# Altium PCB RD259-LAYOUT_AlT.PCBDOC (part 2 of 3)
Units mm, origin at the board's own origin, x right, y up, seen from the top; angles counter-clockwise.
Board outline 82.5 x 69.38 mm, 2 copper layers (TOP, BOTTOM), stack 0 mm thick; 80 components, 51 nets, 446 pads, 0 vias.
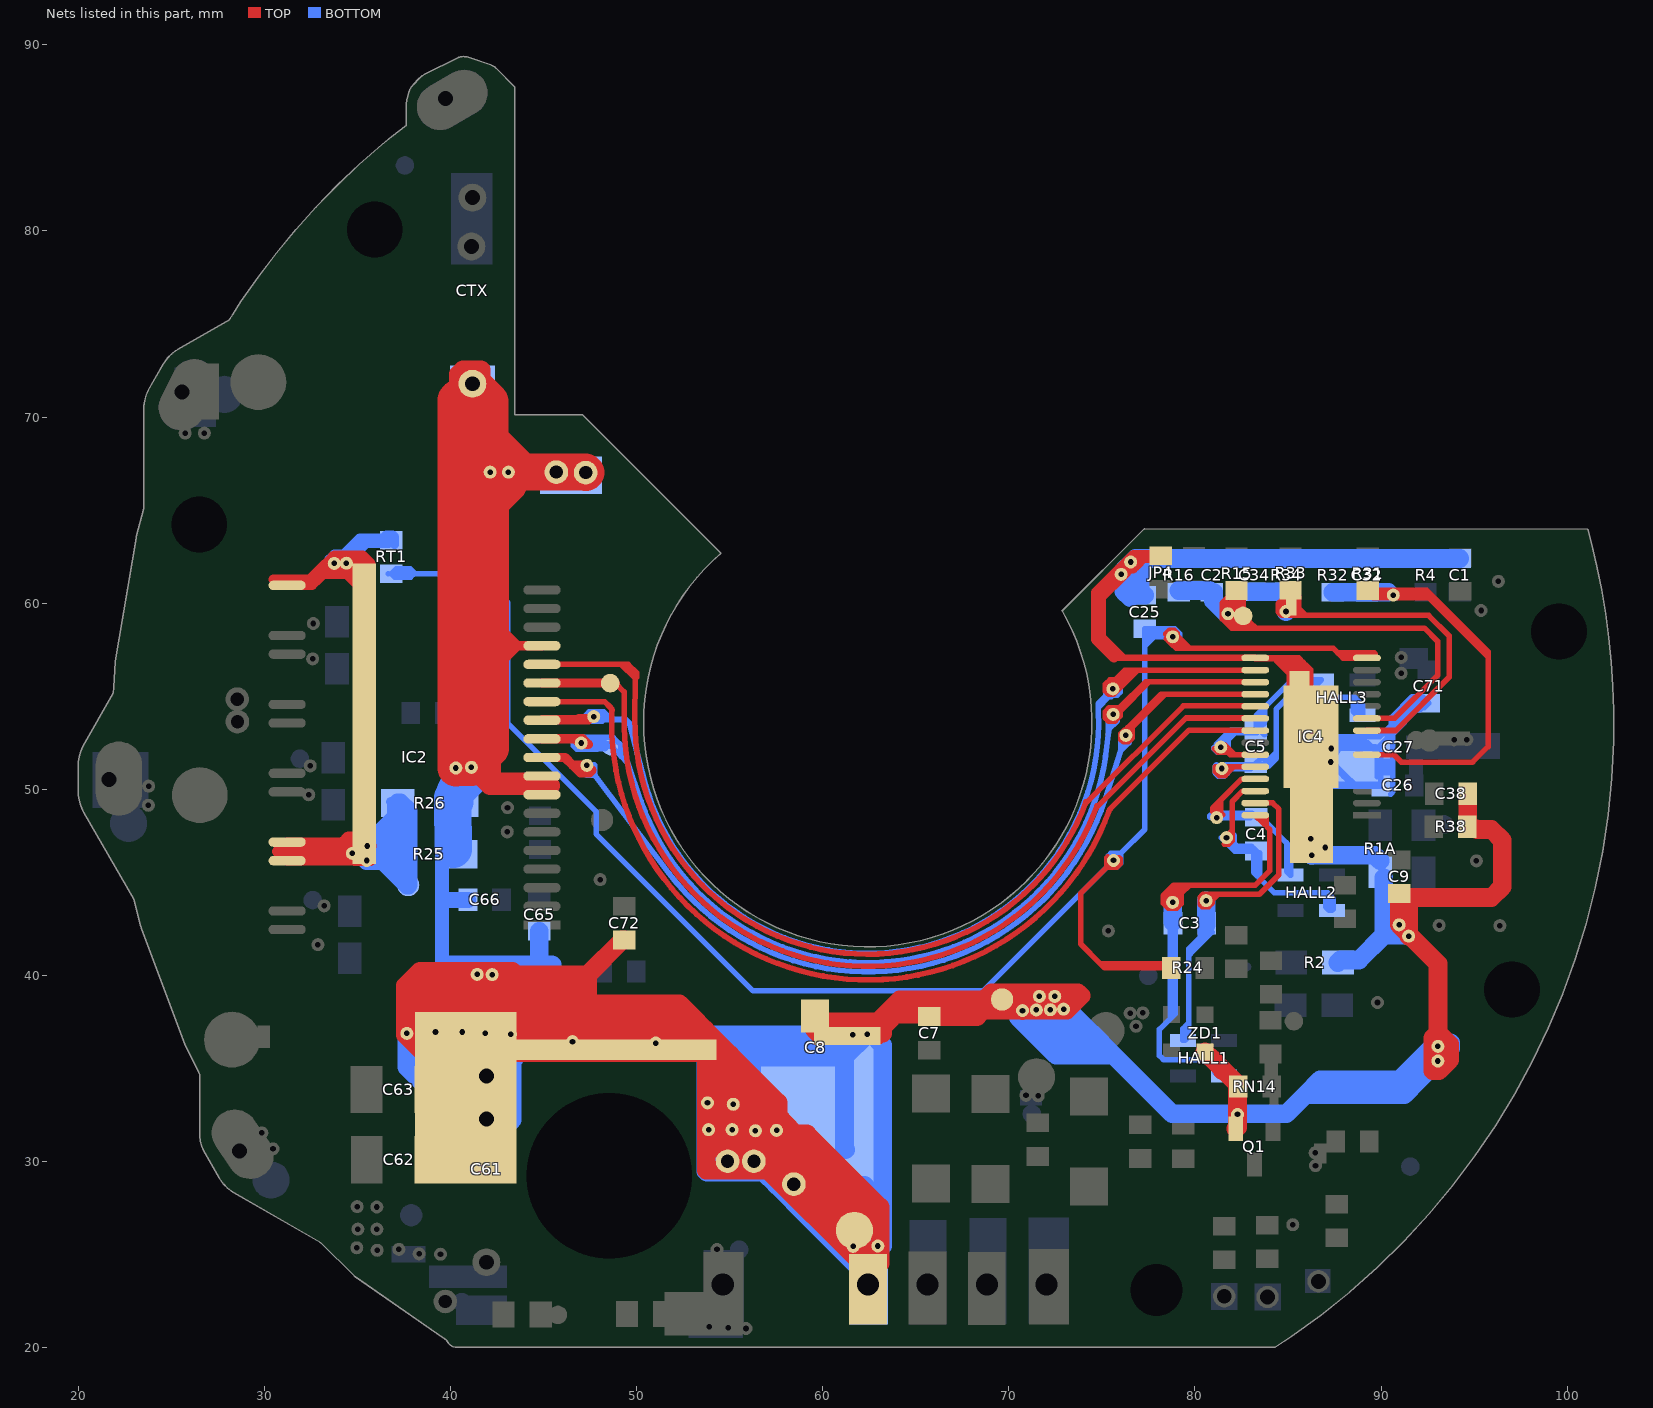
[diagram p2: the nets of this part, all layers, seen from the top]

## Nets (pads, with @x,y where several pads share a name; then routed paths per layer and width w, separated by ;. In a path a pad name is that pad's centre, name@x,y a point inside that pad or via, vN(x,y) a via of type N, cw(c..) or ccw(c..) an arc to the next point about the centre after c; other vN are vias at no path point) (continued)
GND: C1.1 C2.1 C7.2 C8.2 C9.2 C25.1 C26.2 C27.2 C32.1 C34.1 C38.1 C61.2 C62.2 C63.2 C65.2 C66.2 C71.2 C72.2 CTX.1 IC2.8 IC2.9 IC2.16 IC4.0 IC4.15 JP4.1 pad.@37.649,36.874 pad.@39.188,36.951 pad.@40.63,36.951 pad.@40.76,50.903 pad.@40.216,49.798 pad.@40.283,51.138 pad.@40.822,33.413 pad.@41.117,51.174 pad.@41.178,71.75 pad.@41.261,35.528 pad.@41.426,40.045 pad.@41.861,36.874 pad.@41.921,32.277 pad.@42.123,67.039 pad.@42.233,40.033 pad.@43.107,67.039 pad.@43.221,36.827 pad.@45.682,67.039 pad.@46.469,66.874 pad.@46.551,36.43 pad.@47.257,67.014 pad.@48.612,36.006 pad.@51.026,36.357 pad.@53.804,33.143 pad.@53.861,31.701 pad.@54.886,30.006 pad.@55.102,32.403 pad.@55.131,31.701 pad.@55.188,33.066 pad.@55.261,35.775 pad.@56.299,30.006 pad.@56.381,31.643 pad.@57.515,31.662 pad.@58.56,28.481 pad.@58.445,28.774 pad.@58.778,32.166 pad.@61.7,31.399 pad.@61.32,36.748 pad.@61.496,26.989 pad.@61.601,36.796 pad.@61.631,25.431 pad.@61.702,26.285 pad.@62.383,36.821 pad.@62.428,23.378 pad.@62.437,23.124 pad.@62.473,23.419 pad.@62.958,25.451 pad.@69.635,38.699 pad.@70.733,38.103 pad.@71.476,38.136 pad.@71.639,38.867 pad.@72.23,38.147 pad.@72.94,38.181 pad.@72.467,38.867 pad.@73.67,36.682 pad.@76.035,61.546 pad.@76.545,62.21 pad.@77.304,60.424 pad.@82.289,32.52 pad.@85.62,55.925 pad.@86.219,47.345 pad.@86.268,46.441 pad.@86.268,48.487 pad.@87.013,46.868 pad.@87.302,51.46 pad.@87.322,52.184 pad.@88.677,51.366 pad.@90.972,42.707 pad.@90.976,44.393 pad.@91.485,42.1 pad.@93.06,36.176 pad.@93.057,35.391 Q1.3 R1A.1 R2.2 R4.1 R16.1 R25.1 R26.1 R32.1 R34.1 R38.1 RN14.2 ZD1.1 | length 774.4
  TOP w0.3: pad.@42.921,36.021 42.921,35.96 43.145,35.735 43.403,35.477 53.45,35.477 53.746,35.182 ; pad.@62.687,36.873 62.687,36.619 62.86,36.446 63.114,36.446 ; C7.2@65.622,37.782 C7.2@65.722,37.782 ; JP4.1@78.084,62.616 JP4.1@78.156,62.544 ; IC4.15@83.252,57.042 IC4.15@83.242,57.052 85.131,57.052 ; 84.241,57.042 84.465,56.818 ; 85.921,56.515 86.02,56.615 ; pad.@86.268,46.441 86.268,52.801 IC4.0@86.223,52.846 ; 84.465,56.818 84.768,56.515 ; 84.465,56.818 85.07,56.818 ; 84.768,56.515 pad.@85.07,56.213 ; 84.768,56.515 85.07,56.515 ; pad.@85.07,56.213 85.07,53.999 IC4.0@86.223,52.846 ; pad.@85.07,56.213 85.07,56.515 ; 85.07,56.515 85.07,56.818 ; 85.07,56.818 85.07,56.991 85.131,57.052 ; 85.07,56.818 85.818,56.818 ; 85.131,57.052 85.584,57.052 85.818,56.818 ; 85.818,56.818 86.02,56.615 ; 86.02,56.615 86.165,56.47 86.223,56.412 IC4.0@86.223,52.846
  TOP w0.35: 75.648,57.052 76.205,57.052 ; 76.684,61.844 76.631,61.844 76.184,61.397 75.051,60.265 75.051,58.206 76.205,57.052 ; 76.685,61.844 76.798,61.957 76.89,62.049 76.89,62.417 76.89,62.474 76.89,62.616 ; IC4.15@83.242,57.052 76.205,57.052 ; IC4.15@83.252,57.042 84.241,57.042
  TOP w0.4: 42.13,52.186 42.503,51.814 42.503,50.706 ; 42.13,57.549 42.287,57.706 ; IC2.9@44.911,50.706 42.503,50.706 ; pad.@41.195,51.142 42.067,51.142 42.503,50.706 ; pad.@41.195,51.142 41.63,50.706 42.503,50.706 ; pad.@41.195,51.142 41.162,51.174 pad.@41.117,51.174 41.15,51.142 pad.@41.195,51.142
  TOP w0.5: 42.13,56.272 42.165,56.272 43.599,57.706 ; 42.13,58.709 42.596,58.709 43.599,57.706 ; 42.287,57.706 43.599,57.706 ; IC2.16@44.911,57.706 43.599,57.706 ; 75.648,57.052 74.652,58.048 74.652,60.378 ; pad.@76.545,62.21 76.599,62.21 76.806,62.417 76.89,62.417 77.257,62.417 ; 76.684,61.844 76.797,61.957 76.89,62.05 77.257,62.417 ; JP4.1@78.084,62.616 76.89,62.616 ; JP4.1@78.156,62.544 JP4.1@78.086,62.474 ; 85.07,56.515 85.921,56.515 ; 74.652,60.378 75.928,61.653 76.515,62.24 pad.@76.749,62.474 ; 74.652,60.378 74.652,60.586 75.824,61.757 76.41,62.344 76.682,62.616 76.89,62.616 ; pad.@76.749,62.474 76.89,62.474 77.314,62.474 ; pad.@76.749,62.474 76.89,62.616 ; 77.257,62.417 77.314,62.474 ; 77.257,62.417 78.029,62.417 JP4.1@78.086,62.474 ; 77.314,62.474 JP4.1@78.086,62.474
  TOP w1: pad.@39.938,35.874 38.495,35.874 37.572,36.797 37.572,37.24 ; 40.398,71.029 41.191,70.237 ; 40.42,71.051 40.42,72.306 40.662,72.548 41.631,72.548 41.631,71.328 41.631,71.227 41.191,70.787 ; pad.@41.117,51.174 42.114,50.177 45.382,50.177 ; CTX.1@41.191,71.79 41.191,71.768 41.191,70.787 ; pad.@42.233,40.033 43.485,40.033 ; 43.312,39.424 43.304,39.432 ; C72.2@49.333,41.896 49.233,41.896 47.37,40.033 ; pad.@54.886,30.006 57.558,30.006 62.428,25.136 pad.@62.428,24.566 ; pad.@55.188,33.066 56.785,31.47 ; pad.@61.601,36.796 61.678,36.873 pad.@61.945,36.873 ; pad.@61.702,26.285 58.829,29.159 57.287,30.701 53.746,30.701 ; pad.@62.428,23.378 pad.@62.428,24.566 ; pad.@63.073,24.528 63.073,26.758 ; 63.218,36.873 pad.@62.687,36.873 ; 63.229,37.23 63.651,37.651 ; 63.374,37.56 pad.@62.687,36.873 ; C7.2@65.384,38.021 65.28,37.917 63.385,37.917 ; C7.2@65.722,37.782 68.29,37.782 68.642,38.135 pad.@70.764,38.135 ; pad.@70.733,38.103 pad.@70.764,38.135 ; ZD1.1@80.543,35.874 80.882,35.534 80.904,35.534 81.565,34.873 ; 81.481,34.873 81.565,34.873 ; Q1.3@82.196,31.749 82.289,31.842 pad.@82.289,32.52 RN14.2@82.289,34.065 ; RN14.2@82.318,34.02 82.318,34.12 81.565,34.873 ; pad.@91.485,42.1 pad.@91.485,42.194 ; pad.@93.057,35.391 93.057,36.173 pad.@93.06,36.176 93.06,36.916 ; C38.1@94.661,49.748 94.661,48.104 94.641,48.083 R38.1@94.641,47.983 94.641,47.883 95.134,47.883 95.181,47.835 95.934,47.835 96.52,47.25 96.52,44.763 95.934,44.177 pad.@91.292,44.177 ; 37.572,37.24 37.918,37.586 43.391,37.586 43.685,37.291 43.891,37.086 ; 37.572,37.24 37.572,38.499 ; 37.572,38.499 37.736,38.499 ; 37.572,38.499 37.572,39.432 ; 37.572,39.432 43.304,39.432 ; 37.572,39.432 38.353,40.213 43.305,40.213 43.485,40.033 ; 37.736,38.499 38.207,38.028 pad.@42.536,38.028 ; 37.736,38.499 37.827,38.59 42.705,38.59 ; 41.191,67.971 41.191,70.237 ; 41.191,67.971 41.191,67.332 41.483,67.039 pad.@42.123,67.039 41.191,67.971 ; 41.191,70.237 41.191,70.787 ; pad.@42.536,38.028 43.891,38.028 ; pad.@42.536,38.028 42.79,37.774 43.891,37.774 ; 42.705,38.59 43.891,38.59 ; 42.705,38.59 42.833,38.462 43.891,38.462 ; 43.304,39.432 43.891,39.432 ; 43.485,40.033 47.37,40.033 ; 43.485,40.033 43.891,39.627 43.891,39.432 ; 43.891,37.086 53.669,37.086 ; 43.891,37.086 42.034,37.086 42.293,36.827 pad.@43.221,36.827 44.149,36.827 ; 43.891,37.086 44.149,36.827 ; 43.891,37.086 43.891,37.774 ; 43.891,37.774 52.981,37.774 ; 43.891,37.774 43.891,38.028 ; 43.891,38.028 43.891,38.462 ; 43.891,38.462 47.18,38.462 ; 43.891,38.462 43.891,38.59 ; 43.891,38.59 43.891,39.432 ; 43.891,39.432 47.246,39.432 47.37,39.308 ; 44.149,36.827 51.026,36.827 53.283,36.827 54.371,35.739 ; 47.18,38.462 52.293,38.462 52.981,37.774 ; 47.18,38.462 47.37,38.651 47.37,39.308 ; 47.37,39.308 47.37,40.033 ; 52.981,37.774 53.669,37.086 ; 53.669,37.086 55.015,35.739 ; 53.746,30.701 pad.@53.746,31.393 ; 53.746,30.701 53.746,29.528 57.073,29.528 62.035,24.566 pad.@62.428,24.566 ; pad.@53.746,31.393 53.746,35.182 53.746,35.739 54.371,35.739 ; pad.@53.746,31.393 53.823,31.47 54.708,31.47 ; 54.371,35.739 54.515,35.739 ; 54.515,35.739 54.515,31.662 54.708,31.47 ; 54.515,35.739 55.015,35.739 ; 54.708,31.47 56.073,31.47 ; 54.708,31.47 54.708,32.836 ; 54.708,32.836 54.833,32.711 55.486,32.057 56.073,31.47 ; 54.708,32.836 54.708,32.951 ; 54.708,32.836 54.65,32.893 54.708,32.951 ; 54.708,32.951 55.006,33.249 55.265,33.509 55.265,33.893 55.64,33.518 56.948,32.211 pad.@57.688,31.47 ; 54.708,32.951 54.708,34.336 55.15,34.778 55.15,34.874 57.592,32.432 ; 55.015,35.739 57.592,33.162 57.592,32.432 ; 56.073,31.47 56.785,31.47 ; 56.785,31.47 pad.@57.688,31.47 ; 57.592,32.432 57.823,32.201 57.823,32.182 ; 57.592,32.432 57.592,32.412 57.823,32.182 ; pad.@57.688,31.47 57.823,31.47 ; 57.823,31.47 57.823,32.182 ; 57.823,31.47 62.535,26.758 63.073,26.758 ; 57.823,31.47 58.535,31.47 ; 57.823,32.182 57.929,32.076 58.535,31.47 ; 58.535,31.47 59.15,31.47 63.073,27.547 63.073,26.758 ; pad.@61.945,36.873 pad.@62.687,36.873 ; pad.@61.945,36.873 62.138,37.066 62.388,37.316 62.388,37.496 ; pad.@61.945,36.873 61.819,36.748 pad.@61.32,36.748 60.05,36.748 59.967,36.83 59.795,36.83 59.533,37.092 59.533,37.234 59.795,37.496 62.388,37.496 ; 62.388,37.496 62.964,37.496 63.385,37.917 ; 63.385,37.917 64.146,38.678 68.675,38.678 69.066,39.069 pad.@71.698,39.069 ; pad.@70.764,38.135 73.12,38.135 73.878,38.893 73.702,39.069 pad.@71.698,39.069 ; pad.@70.764,38.135 pad.@71.698,39.069 ; pad.@91.292,44.177 91.076,44.393 pad.@90.976,44.393 90.976,42.711 pad.@90.972,42.707 pad.@91.485,42.194 ; pad.@91.292,44.177 91.485,43.984 pad.@91.485,42.194 ; pad.@91.485,42.194 93.06,40.619 93.06,36.916 ; 93.06,36.916 93.693,36.284 93.693,35.455 93.343,35.105 93.107,34.869 92.773,34.869 92.773,36.629 93.06,36.916
  TOP w2: 40.42,71.051 40.398,71.029 40.283,70.914 pad.@40.283,51.138 40.319,51.174 pad.@41.117,51.174 42.13,52.186 42.13,56.272 42.13,57.549 42.13,58.709 42.13,65.408 ; CTX.1@41.169,71.79 41.191,71.768 41.631,71.328 42.123,70.836 42.123,68.741 ; pad.@47.257,67.014 47.231,67.039 pad.@45.682,67.039 43.824,67.039 ; pad.@42.123,67.039 42.123,68.741 ; pad.@42.123,67.039 pad.@43.107,67.039 ; pad.@42.123,67.039 42.13,67.032 42.13,65.408 ; 42.123,68.741 43.466,67.398 43.824,67.039 ; 42.13,65.408 43.107,66.386 pad.@43.107,67.039 ; pad.@43.107,67.039 43.824,67.039
  BOTTOM w0.3: pad.@76.873,60.327 pad.@76.973,60.327 ; 77.256,62.21 77.304,62.162 ; 78.438,62.21 R16.1@78.625,62.397 ; 86.934,52.356 87.042,52.464 87.168,52.59 87.392,52.814 89.929,52.814 90.563,53.448 ; pad.@88.765,52.184 88.979,52.184 89.037,52.242 89.07,52.275 89.07,52.49 89.285,52.49 89.533,52.242 89.543,52.232 89.606,52.169 89.8,51.975 pad.@89.8,50.67 ; C26.2@89.987,50.201 pad.@89.987,51.067 ; 90.529,49.736 90.574,49.781 90.574,49.813 90.632,49.871 90.632,50.879 ; pad.@89.844,52.242 C27.2@89.679,52.242 89.987,51.934 pad.@89.987,51.501 ; pad.@89.844,52.242 89.894,52.242 90.632,52.979 ; pad.@89.844,52.242 90.329,52.727 90.329,52.92 ; pad.@89.987,51.067 pad.@89.987,51.284 ; pad.@89.987,51.067 90.099,51.179 90.632,51.179 ; pad.@89.987,51.067 90.175,50.879 90.632,50.879 ; pad.@89.987,51.284 pad.@89.987,51.501 ; pad.@89.987,51.284 90.042,51.339 90.632,51.339 ; pad.@89.987,51.501 89.989,51.499 90.632,51.499 ; 90.329,52.92 90.329,53.114 90.563,53.348 ; 90.329,52.92 91.683,54.275 91.927,54.275 ; 90.563,53.348 90.563,53.448 ; 90.563,53.348 91.594,54.379 ; 90.563,53.448 90.563,53.861 91.676,54.975 92.217,54.975 C71.2@92.379,54.812 ; 90.563,53.448 91.927,54.812 C71.2@92.379,54.812 ; 90.632,50.879 90.632,51.179 ; 90.632,51.179 90.632,51.339 ; 90.632,51.339 90.632,51.499 ; 90.632,51.499 90.632,52.979 ; 90.632,52.979 91.927,54.275 ; 91.594,54.379 91.84,54.625 C71.2@92.203,54.625 ; 91.594,54.379 C71.2@92.203,54.379 ; 91.927,54.275 92.117,54.275 92.203,54.361 C71.2@92.203,54.379 ; C71.2@92.203,54.379 C71.2@92.203,54.625 ; C71.2@92.203,54.379 92.321,54.379 C71.2@92.567,54.625 ; C71.2@92.203,54.625 C71.2@92.567,54.625 ; C71.2@92.379,54.812 C71.2@92.567,54.625
  BOTTOM w0.4: 86.934,52.356 86.934,50.442 87.174,50.201 88.561,50.201 ; 87.168,52.59 87.196,52.59 ; pad.@87.258,52.242 pad.@87.286,52.242 ; pad.@87.322,52.184 pad.@87.322,51.749 ; pad.@87.628,52.055 87.54,51.967 pad.@87.322,51.749 ; pad.@88.765,52.184 pad.@88.822,52.242 ; C27.2@89.679,52.242 89.533,52.242 89.037,52.242 pad.@88.822,52.242 ; C26.2@89.987,50.201 88.561,50.201 ; 87.196,52.59 89.029,52.59 89.07,52.549 89.07,52.49 pad.@88.822,52.242 ; 87.196,52.59 87.196,52.332 pad.@87.286,52.242 ; pad.@87.286,52.242 88.677,52.242 pad.@88.822,52.242 ; pad.@87.322,51.749 87.322,51.48 pad.@87.302,51.46 88.036,50.725 88.561,50.201
  BOTTOM w0.5: pad.@70.733,38.103 70.804,38.032 71.734,37.102 72.327,36.509 72.767,36.069 ; 73.13,35.706 72.767,36.069 ; 75.466,35.706 75.466,35.868 75.466,36.069 75.265,36.069 72.767,36.069 ; pad.@76.545,62.21 76.629,62.21 77.256,62.21 78.438,62.21 ; pad.@77.304,60.424 77.304,62.162 ; pad.@82.26,32.548 pad.@82.289,32.52 ; 88.756,34.377 88.978,34.599
  BOTTOM w0.762: 39.542,38.845 39.542,46.505 R25.1@40.543,46.505
  BOTTOM w0.864: 39.588,44.052 C66.2@40.932,44.052
  BOTTOM w1: 38.689,36.951 38.689,35.193 ; 38.881,37.251 38.076,36.447 37.866,36.236 37.646,36.236 ; pad.@39.072,36.951 pad.@39.188,36.951 ; 39.663,40.559 40.739,40.559 ; pad.@41.426,40.045 43.402,40.045 ; pad.@41.921,32.277 41.333,32.864 39.851,32.864 ; pad.@42.123,67.039 pad.@43.107,67.039 ; 42.871,38.01 43.307,37.574 43.603,37.278 52.88,37.278 ; pad.@43.275,36.827 43.248,36.8 pad.@42.957,36.509 ; 44.756,40.045 43.402,40.045 ; C65.2@44.77,42.361 44.77,40.559 ; pad.@55.246,34.913 54.822,35.336 54.552,35.606 ; 56.177,33.478 56.299,33.355 ; 56.176,33.478 56.176,35.606 ; pad.@57.753,31.901 56.299,33.355 ; pad.@58.403,28.732 56.299,30.835 ; pad.@61.203,26.984 60.022,26.984 ; pad.@61.223,30.613 61.169,30.667 pad.@61.169,35.606 ; pad.@62.244,28.723 59.998,28.723 ; pad.@62.428,23.378 pad.@62.428,23.804 ; pad.@70.993,38.07 72.23,38.07 pad.@73.012,38.07 ; 75.466,35.706 73.13,35.706 72.541,35.706 71.737,36.509 ; pad.@77.204,60.424 77.204,60.524 76.629,61.098 pad.@76.629,62.21 ; pad.@77.304,60.424 76.671,60.424 76.535,60.288 76.181,60.642 76.181,61.761 pad.@76.629,62.21 ; pad.@82.26,32.548 78.786,32.548 75.466,35.868 75.265,36.069 74.803,36.532 ; pad.@82.343,32.558 84.918,32.558 85.946,33.586 ; pad.@86.219,47.345 pad.@86.268,47.296 ; R2.2@87.686,40.685 87.821,40.82 88.817,40.82 90.145,42.148 ; R1A.1@89.956,46.145 89.66,46.441 87.123,46.441 ; R1A.1@90.145,45.235 90.145,42.727 ; pad.@93.06,36.176 pad.@93.06,35.394 ; C1.1@94.227,62.397 R4.1@92.395,62.397 84.907,62.397 C2.1@80.898,62.397 R16.1@79.125,62.397 78.625,62.397 76.816,62.397 pad.@76.629,62.21 ; 37.646,36.236 37.646,37.298 39.185,38.837 40.225,38.837 40.415,38.646 45.974,38.646 ; 37.646,36.236 38.689,35.193 ; 37.646,36.236 37.646,35.07 38.689,34.027 ; 38.689,34.027 39.224,33.491 39.851,32.864 ; 38.689,34.027 38.689,35.193 ; 39.851,32.864 40.647,32.068 ; 39.851,32.864 40.111,33.124 42.888,33.124 ; 40.647,32.068 42.625,32.068 42.888,31.805 ; 40.647,32.068 41.18,31.536 41.308,31.407 42.491,31.407 42.641,31.557 42.888,31.805 ; 40.739,40.559 42.233,40.559 43.916,40.559 ; 40.739,40.559 40.212,40.032 41.072,39.173 45.447,39.173 ; 42.888,31.805 42.888,33.124 ; 42.888,31.805 43.316,32.232 43.316,35.437 43.706,35.827 ; 42.888,33.124 42.957,33.124 pad.@42.957,34.044 ; 42.888,33.124 42.888,34.001 42.931,34.044 pad.@42.957,34.044 ; pad.@42.957,34.044 pad.@42.957,35.853 ; pad.@42.957,35.853 42.983,35.827 43.706,35.827 ; pad.@42.957,35.853 pad.@42.957,36.509 ; pad.@42.957,36.509 43.03,36.436 46.551,36.436 51.979,36.436 ; 43.402,40.045 43.916,40.559 ; 43.706,35.827 53.672,35.827 53.723,35.777 ; 43.916,40.559 44.77,40.559 ; 44.77,40.559 45.447,40.559 45.447,39.173 ; 45.447,39.173 45.974,38.646 ; 45.974,38.646 46.5,38.12 52.038,38.12 52.88,37.278 ; 51.979,36.436 53.723,36.436 ; 51.979,36.436 52.339,36.796 53.362,36.796 ; 52.88,37.278 53.362,36.796 ; 53.362,36.796 pad.@61.601,36.796 ; 53.362,36.796 53.723,36.436 ; 53.723,35.777 53.723,29.47 53.78,29.412 pad.@56.82,29.412 ; 53.723,35.777 53.723,36.436 ; 53.723,36.436 60.836,36.436 pad.@61.038,36.233 ; 53.723,36.436 54.552,35.606 ; 54.552,35.606 56.176,35.606 ; 56.176,35.606 pad.@60.411,35.606 ; 56.299,30.835 56.299,32.166 56.299,33.355 ; 56.299,30.835 pad.@56.299,30.006 56.299,29.933 56.422,29.81 pad.@56.82,29.412 ; pad.@56.82,29.412 57.509,28.723 ; 57.509,28.723 59.249,28.723 ; 57.509,28.723 59.249,26.984 ; 59.249,26.984 pad.@62.428,23.804 ; 59.249,26.984 59.249,28.723 ; 59.249,26.984 60.022,26.984 ; 59.249,28.723 59.998,28.723 ; 59.998,28.723 60.022,28.699 60.022,26.984 ; pad.@60.411,35.606 pad.@61.169,35.606 ; pad.@60.411,35.606 pad.@61.038,36.233 ; pad.@61.038,36.233 pad.@61.601,36.796 ; pad.@61.169,35.606 pad.@62.383,36.821 ; pad.@61.601,36.796 61.626,36.821 pad.@62.383,36.821 ; pad.@62.383,36.821 62.641,36.821 63.227,36.235 63.227,25.462 62.428,24.662 pad.@62.428,23.804 ; pad.@70.953,38.181 pad.@72.94,38.181 pad.@73.153,38.181 ; pad.@70.953,38.181 pad.@71.639,38.867 pad.@72.467,38.867 72.708,38.626 pad.@73.153,38.181 ; pad.@70.953,38.181 70.804,38.032 70.509,37.737 71.145,37.102 ; 71.145,37.102 71.734,37.102 73.724,37.102 73.978,37.356 ; 71.145,37.102 71.737,36.509 ; 71.737,36.509 72.327,36.509 74.78,36.509 74.803,36.532 ; pad.@73.153,38.181 73.978,37.356 ; 73.978,37.356 74.803,36.532 ; 85.946,33.586 86.737,34.377 88.756,34.377 90.989,34.377 ; 85.946,33.586 91.253,33.586 92.043,34.377 ; pad.@86.268,47.296 86.695,46.868 87.123,46.441 ; pad.@86.268,47.296 pad.@86.268,46.441 87.123,46.441 ; 90.145,42.148 90.145,42.727 ; 90.145,42.148 91.437,42.148 pad.@91.485,42.1 91.485,42.194 pad.@90.972,42.707 90.166,42.707 90.145,42.727 ; 90.989,34.377 92.53,35.918 92.981,36.369 93.735,36.369 93.735,36.068 pad.@93.06,35.394 ; 90.989,34.377 92.043,34.377 ; 92.043,34.377 pad.@93.057,35.391 pad.@93.06,35.394
  BOTTOM w2: 38.881,37.251 39.114,37.023 pad.@39.188,36.951 39.492,37.261 39.894,37.672 40.225,38.01 ; pad.@40.113,49.549 40.116,49.252 R25.1@40.142,46.771 ; 40.212,40.032 40.225,38.837 40.225,38.01 ; pad.@40.216,49.323 pad.@40.216,49.798 ; 45.677,37.685 45.352,38.01 42.871,38.01 41.861,38.01 40.225,38.01 ; pad.@40.216,49.798 pad.@40.76,50.903 40.937,51.263 40.967,51.324 pad.@41.117,51.174 41.117,50.699 40.919,50.501 pad.@40.216,49.798
HU: IC2.13 IC4.21 | length 52.7
  TOP w0.3: IC2.13@44.911,54.706 48.275,54.706 48.58,54.402 48.668,54.314 48.668,54.19 48.668,54.182 ; 48.671,54.248 ccw(c62.431,53.527) 48.668,54.182 ; 75.379,48.815 cw(c62.431,53.527) 48.668,54.182 ; 75.434,48.93 79.681,53.178 IC4.21@83.153,53.178
HUM: C3.2 HALL1.2 IC4.28 pad.@78.799,43.921 | length 38.9
  TOP w0.3: pad.@78.739,44.197 79.063,44.521 ; 78.289,44.078 78.289,44.279 ; 78.289,44.078 78.369,43.998 pad.@78.474,43.998 ; 78.289,44.078 78.289,43.877 78.557,43.609 79.023,43.609 79.261,43.847 79.261,44.383 ; 78.289,44.279 78.333,44.279 ; 78.289,44.279 78.854,44.845 ; 78.333,44.279 78.432,44.379 78.854,44.379 ; 78.333,44.279 pad.@78.544,44.068 ; pad.@78.474,43.998 pad.@78.544,44.068 ; pad.@78.474,43.998 pad.@78.614,43.998 ; pad.@78.544,44.068 78.598,44.122 78.854,44.379 ; pad.@78.544,44.068 pad.@78.614,43.998 ; pad.@78.614,43.998 78.691,43.921 pad.@78.799,43.921 ; pad.@78.614,43.998 78.723,43.998 pad.@78.799,43.921 ; pad.@78.799,43.921 79.261,44.383 ; 78.854,44.379 78.854,44.729 ; 78.854,44.729 78.854,44.845 ; 78.854,44.729 79.063,44.521 ; 78.854,44.845 79.387,44.845 ; 79.063,44.521 79.387,44.845 ; 79.261,44.383 79.723,44.845 ; 79.387,44.845 79.723,44.845 ; 79.723,44.845 83.249,44.845 84.012,45.608 84.012,47.832 83.827,48.017 ; IC4.28@83.653,48.602 IC4.28@83.242,48.602 83.676,48.168 ; IC4.28@83.653,48.602 83.676,48.579 83.676,48.168 ; IC4.28@83.653,48.602 83.804,48.602 83.827,48.579 83.827,48.017 ; 83.676,48.168 83.827,48.017
  BOTTOM w0.3: C3.2@78.715,42.78 78.774,42.84 C3.2@78.799,42.865 ; C3.2@78.824,42.79 78.684,42.65 78.684,37.781 78.735,37.731 ; C3.2@78.933,42.799 78.933,37.929 78.735,37.731 ; HALL1.2@81.573,34.597 HALL1.2@81.504,34.597 ; 81.879,34.975 81.551,34.975 81.304,35.222 ; 78.735,37.731 78.092,37.088 78.092,35.685 78.31,35.467 80.724,35.467 ; 80.724,35.467 81.059,35.467 ; 80.724,35.467 81.059,35.132 ; 81.059,35.132 81.059,35.467 ; 81.059,35.132 81.059,34.797 81.259,34.597 HALL1.2@81.504,34.597 ; 81.059,35.467 81.304,35.222 ; 81.304,35.222 81.304,34.797 HALL1.2@81.504,34.597
  BOTTOM w1: C3.2@78.799,42.865 pad.@78.799,43.921
HUP: C3.1 HALL1.4 IC4.27 pad.@80.601,44.008 | length 24.9
  TOP w0.3: pad.@80.601,44.008 80.639,44.008 80.976,44.345 ; IC4.27@83.163,49.268 84.179,49.268 84.512,48.936 84.512,45.401 83.456,44.345 81.229,44.345 ; 80.976,44.345 80.436,44.345 80.35,44.259 80.287,44.196 80.281,44.196 80.281,43.81 80.402,43.689 80.734,43.689 80.932,43.887 80.932,44.047 81.229,44.345 ; 80.976,44.345 81.229,44.345
  BOTTOM w0.3: C3.1@80.627,42.79 80.601,42.763 80.277,42.44 80.277,42.033 ; C3.1@80.71,42.709 80.708,42.708 80.66,42.66 80.66,42.416 80.277,42.033 ; C3.1@80.92,42.319 79.771,41.171 79.661,41.171 ; HALL1.4@79.353,36.697 79.353,37.122 79.507,37.275 ; HALL1.4@79.353,36.697 HALL1.4@79.507,36.697 ; HALL1.4@79.353,36.697 79.353,36.502 HALL1.4@79.348,36.497 79.461,36.497 HALL1.4@79.507,36.544 ; HALL1.4@79.507,36.544 HALL1.4@79.507,36.697 ; HALL1.4@79.507,36.544 HALL1.4@79.661,36.697 ; HALL1.4@79.507,36.697 79.507,37.275 ; HALL1.4@79.507,36.697 HALL1.4@79.661,36.697 ; 79.507,37.275 79.661,37.429 ; HALL1.4@79.661,36.697 79.661,37.429 ; 79.661,37.429 79.661,41.171 ; 79.661,41.171 79.661,41.417 80.277,42.033
  BOTTOM w1: C3.1@80.601,42.7 80.601,42.763 pad.@80.601,44.008
HV: IC2.14 IC4.20 pad.@48.577,55.698 | length 53.3
  TOP w0.3: pad.@48.849,55.706 49.322,55.233 49.322,53.363 ; 49.323,53.348 ccw(c62.421,53.577) 74.731,49.097 ; 74.719,49.016 79.531,53.828 IC4.20@83.153,53.828
  TOP w0.5: IC2.14@44.911,55.706 pad.@48.849,55.706
HVM: C4.2 HALL2.2 IC4.26 pad.@81.697,47.398 | length 21.7
  TOP w0.3: 81.574,47.053 81.823,47.053 82.005,47.236 82.005,47.773 ; pad.@81.697,47.398 81.697,47.465 82.005,47.773 ; IC4.26@83.242,49.902 83.232,49.892 82.565,49.892 82.005,49.332 82.005,47.773
  BOTTOM w0.3: pad.@81.42,47.389 81.554,47.255 82.129,46.68 C4.2@83.288,46.68 ; pad.@81.697,47.398 81.805,47.398 82.11,47.093 ; 82.027,47.593 82.11,47.51 82.11,47.093 ; C4.2@83.472,46.571 83.472,45.221 ; 82.11,47.093 82.262,46.941 ; 82.262,46.941 82.414,46.789 C4.2@83.18,46.789 ; 82.262,46.941 83.028,46.941 C4.2@83.18,46.789 ; C4.2@83.18,46.789 C4.2@83.288,46.68 ; C4.2@83.288,46.68 83.164,46.555 83.164,45.529 83.318,45.375 ; C4.2@83.288,46.68 83.318,46.65 83.318,45.375 ; 83.318,45.375 83.472,45.221 ; 83.472,45.221 84.27,44.423 86.805,44.423 ; 86.805,44.423 87.02,44.208 ; 86.805,44.423 87.144,44.423 87.435,44.133 87.435,43.558 HALL2.2@87.359,43.483 ; 87.02,44.208 87.235,43.993 87.235,43.607 HALL2.2@87.359,43.483 ; 87.02,44.208 87.02,43.683 87.22,43.483 HALL2.2@87.359,43.483
HVP: C4.1 HALL2.4 IC4.25 pad.@81.166,48.471 | length 15.5
  TOP w0.3: 81.491,48.624 81.39,48.725 81.39,49.424 ; IC4.25@83.242,50.552 83.232,50.542 82.508,50.542 81.39,49.424 ; 81.237,49.271 80.951,48.986 80.951,48.794 81.166,48.579 pad.@81.166,48.471 81.237,48.542 81.237,49.271 ; 81.237,49.271 81.39,49.424
  BOTTOM w0.3: 80.808,48.493 80.808,48.576 80.934,48.703 81.053,48.822 81.261,48.822 81.379,48.703 82.071,48.703 ; pad.@81.166,48.471 82.071,48.471 ; 82.081,48.713 82.071,48.703 ; C4.1@82.976,48.471 82.071,48.471 ; C4.1@83.288,48.483 83.068,48.703 82.071,48.703 ; C4.1@83.646,48.385 84.925,47.106 ; HALL2.4@85.134,45.383 85.125,45.383 84.925,45.583 84.925,47.106 ; HALL2.4@85.142,45.383 85.142,46.889 84.925,47.106 ; 82.071,48.471 82.071,48.703
HW: IC2.15 IC4.19 | length 55.2
  TOP w0.3: IC2.15@44.911,56.706 49.165,56.706 ; 49.906,53.858 ccw(c62.413,53.639) 49.905,53.768 ; 74.102,49.199 79.381,54.478 IC4.19@83.153,54.478 ; 74.144,49.326 cw(c62.482,53.57) 71.257,44.795 cw(c62.413,53.639) 49.905,53.768 ; 49.165,56.706 49.927,55.944 ; 49.165,56.706 49.541,56.706 49.991,56.256 49.991,56.008 49.927,55.944 ; 49.905,53.768 49.927,55.944
HWM: C5.2 HALL3.2 IC4.24 pad.@81.45,51.112 | length 24.1
  TOP w0.3: pad.@81.45,51.112 81.558,51.112 81.649,51.202 82.08,51.202 ; IC4.24@83.242,51.202 82.08,51.202 ; 82.08,51.202 81.72,50.842 81.602,50.724 81.315,50.724 81.189,50.85 81.104,50.935 81.098,50.935 81.098,51.203 81.092,51.21 82.072,51.21 82.08,51.202
  BOTTOM w0.3: 81.159,51.321 81.082,51.245 81.082,50.868 81.261,50.689 81.573,50.689 81.723,50.839 81.995,51.112 ; 81.995,51.112 pad.@81.45,51.112 81.649,51.31 C5.2@83.209,51.31 ; 81.995,51.112 83.01,51.112 C5.2@83.209,51.31 ; C5.2@83.209,51.31 C5.2@83.331,51.31 ; C5.2@83.209,51.31 C5.2@83.27,51.371 ; C5.2@83.27,51.371 C5.2@83.331,51.31 ; C5.2@83.27,51.371 83.545,51.646 84.033,51.646 ; C5.2@83.331,51.31 83.415,51.225 83.942,51.225 84.369,51.652 84.369,51.982 ; C5.2@83.331,51.31 83.697,51.31 84.033,51.646 ; 84.033,51.646 84.369,51.982 ; 84.369,51.982 84.369,54.304 85.017,54.952 88.216,54.952 ; 88.216,54.952 88.501,54.666 ; 88.216,54.952 88.585,54.952 89.03,54.506 89.03,53.992 HALL3.2@89.012,53.974 HALL3.2@88.987,53.974 ; 88.501,54.666 88.501,54.174 88.701,53.974 HALL3.2@88.987,53.974 ; 88.501,54.666 88.787,54.38 88.787,54.174 HALL3.2@88.987,53.974
HWP: C5.1 HALL3.4 IC4.23 pad.@81.388,52.259 | length 19.8
  TOP w0.3: 81.031,52.182 81.171,52.042 81.222,51.991 81.765,51.991 ; pad.@81.388,52.259 81.497,52.259 81.765,51.991 ; pad.@81.577,52.388 82.113,51.852 ; IC4.23@83.242,51.852 82.113,51.852 ; 81.765,51.991 81.904,51.852 82.113,51.852
  BOTTOM w0.3: 81.018,52.234 81.018,52.167 81.158,52.028 81.194,51.992 81.644,51.992 81.644,52.03 81.775,52.161 81.775,52.646 ; pad.@81.143,52.397 81.196,52.451 81.92,53.175 C5.1@83.27,53.175 ; pad.@81.388,52.259 81.775,52.646 ; C5.1@83.453,53.204 C5.1@83.475,53.182 ; C5.1@83.74,52.917 C5.1@83.475,53.182 ; 81.775,52.646 82.162,53.033 83.326,53.033 83.369,53.076 C5.1@83.475,53.182 ; C5.1@83.27,53.175 C5.1@83.293,53.198 ; C5.1@83.27,53.175 83.37,53.175 83.72,53.525 83.72,53.625 83.737,53.642 83.737,54.393 ; C5.1@83.293,53.198 83.293,53.949 83.508,54.163 ; C5.1@83.293,53.198 83.508,53.413 83.508,54.163 ; 83.508,54.163 83.737,54.393 ; 83.737,54.393 85.061,55.716 ; 85.061,55.716 85.218,55.874 HALL3.4@86.787,55.874 86.63,55.716 85.061,55.716
IDC: C25.2 IC4.14 pad.@75.626,46.17 pad.@78.806,58.19 R24.1 RT1.1 | length 114.7
  TOP w0.3: 75.312,46.359 75.268,46.315 ; pad.@75.626,46.17 75.268,45.813 ; 75.975,46.265 75.975,46.256 75.971,46.253 ; 78.442,58.328 78.442,58.347 78.545,58.45 78.646,58.552 78.879,58.552 79.055,58.376 79.055,58.222 79.7,57.577 ; pad.@78.471,58.093 78.59,57.975 78.776,57.789 ; pad.@78.806,58.19 78.831,58.19 79.108,57.914 ; IC4.14@89.242,57.052 87.956,57.052 87.689,57.319 ; 89.692,57.267 89.64,57.319 87.689,57.319 ; 74.935,40.613 73.856,41.691 73.856,44.4 75.268,45.813 ; 74.935,40.613 75.153,40.394 R24.1@78.72,40.394 78.501,40.613 74.935,40.613 ; 75.268,45.813 75.268,46.315 ; 75.268,45.813 75.795,45.813 75.889,45.906 75.971,45.989 75.971,46.253 ; 75.268,46.315 75.909,46.315 75.971,46.253 ; 78.776,57.789 78.982,57.789 79.095,57.901 79.108,57.914 ; 78.776,57.789 78.988,57.577 79.445,57.577 ; 79.108,57.914 79.445,57.577 ; 79.445,57.577 79.7,57.577 ; 79.7,57.577 87.431,57.577 87.689,57.319
  BOTTOM w0.3: RT1.1@36.656,61.576 RT1.1@36.658,61.578 ; C25.2@77.304,58.536 77.304,58.105 ; pad.@78.806,58.19 pad.@78.784,58.19 ; 79.176,58.178 79.176,58.354 79.073,58.458 79.043,58.487 ; RT1.1@36.816,61.578 38.02,61.578 ; RT1.1@36.816,61.578 37.082,61.845 37.828,61.845 38.094,61.578 ; RT1.1@36.816,61.578 36.99,61.404 37.846,61.404 38.02,61.578 ; 38.02,61.578 38.094,61.578 ; 38.094,61.578 41.529,61.578 43.074,60.034 43.074,53.537 47.818,48.793 47.818,47.595 56.256,39.157 68.616,39.157 75.306,45.846 ; 75.306,45.846 75.835,45.846 75.892,45.903 76.011,46.022 76.011,46.551 ; 75.306,45.846 75.627,46.168 76.011,46.551 ; 75.306,45.846 75.306,46.375 75.482,46.551 76.011,46.551 ; 76.011,46.551 77.304,47.844 77.304,57.686 ; 77.304,57.686 77.771,58.153 C25.2@77.808,58.19 ; 77.304,57.686 77.304,58.105 ; 77.304,58.105 77.389,58.19 C25.2@77.808,58.19 ; C25.2@77.808,58.19 pad.@78.697,58.19 ; 78.267,58.62 C25.2@77.304,58.62 77.437,58.487 78.4,58.487 ; 78.267,58.62 78.354,58.62 ; 78.267,58.62 78.4,58.487 ; 78.354,58.62 78.91,58.62 79.043,58.487 ; 78.354,58.62 78.487,58.487 ; 78.4,58.487 78.487,58.487 ; 78.4,58.487 pad.@78.697,58.19 ; 78.487,58.487 79.043,58.487 ; 78.487,58.487 pad.@78.784,58.19 ; pad.@78.697,58.19 pad.@78.784,58.19
IS: IC2.20 IC2.27 IC2.28 pad.@33.746,62.133 pad.@34.399,62.144 pad.@34.721,46.547 pad.@35.352,54.055 pad.@35.493,46.167 pad.@35.511,46.947 pad.@37.719,44.848 R25.2 R26.2 RT1.2 | length 79.6
  TOP w0.5: 30.452,61.274 30.469,61.29 32.448,61.29 ; IC2.28@31.211,46.156 34.721,46.156 pad.@34.721,46.547 ; IC2.27@31.211,47.156 33.963,47.156 34.181,46.938 ; IC2.20@31.211,60.956 32.57,60.956 32.903,61.29 ; pad.@34.814,46.13 pad.@35.456,46.13 ; pad.@34.94,61.029 34.506,61.463 34.506,61.55 ; pad.@35.276,61.46 pad.@35.276,61.578 ; pad.@35.352,47.035 35.352,46.947 35.352,46.363 pad.@35.585,46.13 ; pad.@35.352,47.106 pad.@35.352,47.319 ; pad.@35.352,54.055 35.352,48.172 35.352,47.348 pad.@35.352,47.319 ; pad.@35.411,61.915 34.79,62.536 34.746,62.58 ; pad.@35.493,46.167 pad.@35.456,46.13 ; pad.@35.699,61.763 35.725,61.788 35.725,62.133 35.278,62.58 34.746,62.58 ; pad.@35.71,46.13 pad.@35.585,46.13 ; 32.448,61.29 33.093,61.935 ; 32.448,61.29 32.903,61.29 ; 32.903,61.29 33.163,61.55 ; 33.093,61.935 33.518,62.36 33.738,62.58 34.746,62.58 ; 33.093,61.935 33.145,61.883 33.496,61.883 ; 33.163,61.55 34.506,61.55 ; 33.163,61.55 33.496,61.883 ; 33.496,61.883 pad.@34.971,61.883 ; 33.496,61.883 pad.@33.746,62.133 34.603,62.133 34.753,61.983 34.871,61.983 pad.@34.971,61.883 ; 34.181,46.938 30.93,46.938 30.68,46.688 30.643,46.65 30.746,46.547 33.893,46.547 pad.@34.667,46.547 ; 34.181,46.938 34.276,46.938 ; 34.276,46.938 34.283,46.938 34.721,46.938 ; 34.276,46.938 34.28,46.934 pad.@34.667,46.547 ; 34.506,61.55 35.248,61.55 pad.@35.276,61.578 ; pad.@34.667,46.547 pad.@34.721,46.547 ; pad.@34.721,46.547 34.721,46.938 ; 34.721,46.938 34.971,46.938 35.246,47.212 pad.@35.352,47.319 ; pad.@34.971,61.883 pad.@35.276,61.578 ; pad.@35.456,46.13 pad.@35.585,46.13
  TOP w1: 33.893,46.547 34.28,46.934 34.283,46.938 34.307,46.961 34.562,47.217 35.221,47.217 35.352,47.348 pad.@35.484,47.48 ; pad.@34.987,46.823 35.221,46.823 35.345,46.947 35.352,46.947 pad.@35.511,46.947 ; pad.@35.352,48.172 35.484,48.04 pad.@35.484,47.48 ; pad.@35.484,47.086 pad.@35.484,47.48
  BOTTOM w0.5: 33.597,61.733 33.597,61.769 ; pad.@35.455,46.205 35.117,46.205 34.775,46.547 35.136,46.908 35.473,46.908 pad.@35.511,46.947 ; R26.2@36.787,49.323 R26.2@37.077,49.033 ; R25.2@36.823,46.771 36.836,46.783 R25.2@37.077,47.025 ; RT1.2@36.983,63.146 36.983,63.57 36.894,63.659 RT1.2@36.538,63.659 ; 33.597,61.769 34.565,61.769 35.157,62.362 35.157,62.891 ; 33.597,61.769 33.49,61.877 33.453,61.913 33.453,62.328 33.502,62.376 33.746,62.621 34.234,62.621 ; 34.234,62.621 34.078,62.465 pad.@33.746,62.133 34.399,62.133 34.405,62.139 35.157,62.891 ; 34.234,62.621 35.112,63.499 36.377,63.499 RT1.2@36.538,63.659 ; 35.157,62.891 35.49,63.224 36.658,63.224 RT1.2@36.816,63.382 RT1.2@36.538,63.659
  BOTTOM w1: pad.@34.721,46.547 34.775,46.547 35.113,46.547 35.455,46.205 pad.@35.493,46.167 ; pad.@35.511,46.947 pad.@35.539,46.975 ; R25.2@36.251,46.975 pad.@35.539,46.975 ; R25.2@37.077,47.025 37.077,48.374 ; R26.2@37.077,49.033 37.077,48.374 ; pad.@35.493,46.167 36.346,46.167 37.664,44.848 pad.@37.719,44.848 37.719,48.84 37.302,49.257 R26.2@37.164,49.257 37.139,49.231 37.139,48.374 ; pad.@35.493,46.167 35.57,46.243 36.852,46.243 R25.2@37.114,46.505 37.139,46.53 37.139,48.374 ; pad.@35.539,46.975 36.938,48.374 37.077,48.374 ; 37.077,48.374 37.139,48.374
LA: C2.2 IC4.9 pad.@80.998,60.593 pad.@81.776,59.429 pad.@82.592,59.314 R15.1 R16.2 | length 38.6
  TOP w0.3: IC4.9@89.242,53.802 89.252,53.811 90.736,53.811 93.039,56.114 93.039,57.949 92.336,58.652 83.273,58.652 ; 81.459,59.161 pad.@82.133,59.161 ; 81.459,59.161 81.459,59.793 ; 81.459,59.161 81.483,59.136 81.713,58.907 ; 81.459,59.793 82.042,59.793 ; 81.459,59.793 81.459,59.999 ; 81.459,59.999 81.875,59.999 82.042,60.166 ; 81.459,59.999 82.138,60.679 R15.1@82.238,60.679 ; 81.713,58.907 81.968,58.652 82.642,58.652 ; 81.713,58.907 82.296,58.907 pad.@82.342,58.952 ; 82.042,59.793 82.042,59.429 82.042,59.253 pad.@82.133,59.161 ; 82.042,59.793 82.042,59.861 ; 82.042,59.793 82.11,59.793 ; 82.042,59.861 82.042,60.166 ; 82.042,59.861 82.11,59.793 ; 82.042,60.166 82.042,60.47 R15.1@82.238,60.667 ; 82.11,59.793 82.125,59.778 82.589,59.314 pad.@82.592,59.314 ; 82.11,59.793 82.218,59.793 82.238,59.813 ; pad.@82.133,59.161 82.286,59.008 pad.@82.342,58.952 ; 82.238,59.813 R15.1@82.238,60.24 ; 82.238,59.813 pad.@82.458,59.594 ; R15.1@82.238,60.24 R15.1@82.238,60.667 ; R15.1@82.238,60.24 82.458,60.021 pad.@82.458,59.594 ; R15.1@82.238,60.667 R15.1@82.238,60.679 ; R15.1@82.238,60.679 82.242,60.679 82.592,60.329 pad.@82.592,59.46 ; pad.@82.342,58.952 82.642,58.652 ; pad.@82.458,59.594 82.458,59.448 pad.@82.592,59.314 ; pad.@82.458,59.594 pad.@82.592,59.46 ; pad.@82.592,59.314 pad.@82.592,59.46 ; pad.@82.592,59.314 82.611,59.314 pad.@82.942,58.983 ; 82.642,58.652 82.642,58.683 82.932,58.973 pad.@82.942,58.983 ; 82.642,58.652 83.273,58.652 ; pad.@82.942,58.983 83.273,58.652
  BOTTOM w0.3: pad.@80.779,60.679 pad.@80.898,60.56 ; pad.@81.667,59.172 81.524,59.172 81.31,59.386 81.31,59.815 81.31,60.243 80.998,60.555 80.96,60.593 pad.@80.998,60.593 81.7,59.892 81.7,59.506 pad.@81.776,59.429
  BOTTOM w1: R16.2@79.125,60.679 pad.@80.779,60.679 ; C2.2@80.898,60.593 pad.@80.96,60.593 ; pad.@80.998,60.593 80.998,60.555 80.998,60.127 81.31,59.815 81.695,59.429 pad.@81.776,59.429
LAOFS: C34.2 IC4.8 pad.@84.893,59.551 pad.@85.181,59.894 R33.1 R34.2 | length 26.9
  TOP w0.3: 84.674,60.159 84.48,59.964 ; pad.@85.142,59.897 85.075,59.964 84.893,59.964 ; IC4.8@89.242,53.152 90.798,53.152 93.67,56.024 93.67,58.237 92.563,59.344 85.967,59.344 ; 84.48,59.742 pad.@84.893,59.742 ; 84.48,59.742 84.48,59.52 84.655,59.344 pad.@85.208,59.344 ; 84.48,59.742 84.48,59.964 ; 84.48,59.964 84.893,59.964 ; pad.@84.893,59.742 85.569,59.742 85.59,59.721 ; pad.@84.893,59.742 84.893,59.964 ; pad.@84.893,59.742 pad.@84.893,59.551 85.001,59.551 pad.@85.208,59.344 ; 84.893,59.964 84.893,60.444 R33.1@85.14,60.691 85.24,60.691 85.59,60.341 85.59,59.721 ; pad.@85.208,59.344 85.731,59.344 ; 85.59,59.721 85.59,59.485 85.731,59.344 ; 85.59,59.721 85.967,59.344 ; 85.731,59.344 85.967,59.344
  BOTTOM w0.3: C34.2@82.976,60.581 C34.2@83.001,60.605 ; R34.2@84.893,60.591 R34.2@84.907,60.605
  BOTTOM w1: C34.2@83.001,60.605 R34.2@84.907,60.605 ; pad.@84.893,59.551 R34.2@84.893,60.591
LATYPE: C32.2 IC4.6 pad.@90.66,60.433 R31.2 R32.2 | length 31.5
  TOP w0.3: IC4.6@89.242,51.852 90.691,51.852 91.089,51.454 94.919,51.454 95.756,52.291 95.756,57.102 ; R31.2@89.579,60.384 R31.2@89.284,60.679 92.464,60.679 92.759,60.384 ; 92.759,60.384 92.474,60.384 95.756,57.102 ; 92.759,60.384 95.756,57.387 95.756,57.102
  TOP w0.5: R31.2@89.579,60.384 92.474,60.384
  BOTTOM w0.3: pad.@90.396,60.588 90.552,60.433 pad.@90.66,60.433
  BOTTOM w1: R32.2@87.415,60.593 C32.2@89.243,60.593 ; C32.2@89.247,60.588 pad.@90.396,60.588
LU: IC2.10 IC4.18 pad.@47.323,51.283 pad.@47.735,50.742 pad.@76.289,52.896 | length 60.5
  TOP w0.3: 76.643,52.796 76.632,52.807 ; IC4.18@83.13,55.102 78.399,55.102 ; pad.@76.366,53.069 76.289,52.993 pad.@76.289,52.896 76.366,52.972 pad.@76.366,53.069 ; pad.@76.366,53.069 76.366,53.29 ; pad.@76.366,53.069 76.632,53.335 ; 76.366,53.29 76.23,53.153 76.198,53.153 76.115,53.07 76.023,52.978 76.023,52.655 76.054,52.655 76.165,52.545 76.413,52.545 76.527,52.658 76.632,52.764 76.632,52.807 ; 76.366,53.29 78.178,55.102 78.399,55.102 ; 76.632,52.807 76.632,53.335 ; 76.632,53.335 78.399,55.102
  TOP w0.5: IC2.10@44.911,51.706 46.142,51.706 46.566,51.283 46.582,51.283 ; pad.@47.323,51.283 46.582,51.283 ; 47.6,51.018 47.466,50.884 46.981,50.884 46.582,51.283
  BOTTOM w0.3: 47.011,51.047 47.049,51.009 47.163,50.895 ; pad.@47.323,51.283 47.579,50.947 ; 47.712,51.307 47.735,51.285 pad.@47.735,50.742 ; 51.719,45.513 ccw(c62.421,53.577) 51.756,45.464 ; 75.164,49.434 76.021,52.071 ; 75.165,49.436 cw(c62.421,53.577) 51.761,45.457 ; pad.@76.021,52.719 76.021,52.071 ; pad.@76.204,52.9 pad.@76.289,52.896 76.021,52.071 ; 76.461,52.583 76.461,52.51 76.021,52.071 ; 47.163,50.895 47.316,50.742 pad.@47.735,50.742 ; 47.163,50.895 47.215,50.947 47.579,50.947 ; 47.579,50.947 pad.@47.735,50.742 ; pad.@47.735,50.742 51.756,45.464 ; 51.756,45.464 ccw(c62.421,53.577) 51.761,45.457 ; 51.756,45.464 51.761,45.457
LV: IC2.11 IC4.17 pad.@47.018,52.48 pad.@48.602,52.317 pad.@75.35,52.941 pad.@75.605,54.02 | length 69.6
  TOP w0.3: IC2.11@44.911,52.706 IC2.11@44.914,52.704 ; pad.@46.91,52.48 pad.@47.018,52.48 ; pad.@75.605,54.02 75.961,54.376 ; 76.057,54.472 75.961,54.376 ; IC4.17@83.153,55.778 77.566,55.778 ; 75.961,54.376 75.394,54.376 75.186,54.169 75.186,53.827 75.362,53.651 75.694,53.651 75.834,53.791 75.975,53.932 75.975,54.186 77.566,55.778 ; 75.961,54.376 77.363,55.778 77.566,55.778
  TOP w0.5: IC2.11@44.914,52.704 46.686,52.704 ; 46.686,52.704 47.103,52.704 47.172,52.634 47.396,52.411 47.396,52.404 46.986,52.404 46.91,52.48 46.686,52.704
  BOTTOM w0.3: 50.223,49.377 ccw(c62.421,53.577) 50.235,49.344 ; 75.195,51.782 cw(c62.421,53.577) 50.235,49.344 ; 75.207,51.868 pad.@75.35,52.941 ; pad.@75.321,53.914 75.35,53.884 75.35,53.198 ; pad.@75.494,54.014 75.442,53.626 ; 75.829,53.677 75.778,53.626 ; 47.583,52.557 47.696,52.67 ; 47.583,52.557 47.688,52.451 47.914,52.451 ; 47.583,52.557 47.094,52.557 pad.@47.018,52.48 47.094,52.404 pad.@48.407,52.404 ; 47.696,52.67 47.809,52.783 ; 47.696,52.67 47.805,52.56 ; 47.805,52.56 48.027,52.783 ; 47.805,52.56 47.914,52.451 ; 47.809,52.783 46.769,52.783 46.742,52.756 46.594,52.607 46.594,52.329 46.769,52.154 47.887,52.154 47.917,52.183 48.295,52.183 pad.@48.461,52.349 ; 47.809,52.783 48.027,52.783 ; 47.914,52.451 pad.@48.359,52.451 ; 48.027,52.783 48.728,52.783 48.898,52.613 49.146,52.365 49.146,51.782 ; 48.027,52.783 pad.@48.359,52.451 ; pad.@48.359,52.451 48.468,52.451 pad.@48.515,52.404 ; pad.@48.359,52.451 pad.@48.407,52.404 ; pad.@48.407,52.404 pad.@48.515,52.404 ; pad.@48.407,52.404 pad.@48.461,52.349 ; pad.@48.461,52.349 pad.@48.515,52.404 ; pad.@48.461,52.349 48.493,52.317 pad.@48.602,52.317 pad.@48.515,52.404 ; pad.@48.515,52.404 48.524,52.404 48.606,52.322 49.146,51.782 ; 49.146,51.782 49.517,51.411 50.235,49.344 ; pad.@75.35,52.941 75.35,53.198 ; pad.@75.35,52.941 75.39,53.238 ; 75.35,53.198 75.39,53.238 ; 75.39,53.238 75.442,53.626 ; 75.39,53.238 75.778,53.626 ; 75.442,53.626 75.778,53.626
LW: IC2.12 IC4.16 pad.@47.692,53.902 pad.@75.593,55.388 | length 68
  TOP w0.3: IC2.12@44.911,53.706 IC2.12@44.93,53.725 ; 46.696,53.725 46.873,53.902 pad.@47.583,53.902 ; pad.@47.407,53.725 pad.@47.583,53.902 ; pad.@47.641,53.852 pad.@47.692,53.902 pad.@47.583,53.902 ; IC4.16@83.242,56.402 76.928,56.402 ; 75.707,55.869 75.425,55.869 75.268,55.713 75.196,55.64 75.196,55.269 75.335,55.13 75.372,55.094 75.62,55.094 75.754,55.227 76.928,56.402 ; 75.707,55.869 75.534,55.696 75.534,55.448 pad.@75.593,55.388 76.606,56.402 ; 75.707,55.869 76.239,56.402 76.606,56.402 ; 76.606,56.402 76.928,56.402
  TOP w0.5: IC2.12@44.93,53.725 46.696,53.725 pad.@47.407,53.725
  BOTTOM w0.3: 50.438,50.386 49.59,53.571 49.414,53.747 48.641,53.747 ; 50.443,50.368 ccw(c62.421,53.577) 74.809,54.103 ; 74.804,54.226 cw(c62.421,53.577) 74.809,54.125 ; pad.@75.593,55.388 75.199,54.995 ; pad.@47.692,53.902 pad.@47.83,53.871 ; pad.@47.692,53.902 pad.@47.791,53.902 ; pad.@47.692,53.902 47.738,53.948 pad.@47.838,53.948 ; pad.@47.791,53.902 pad.@47.838,53.948 ; pad.@47.791,53.902 47.8,53.902 pad.@47.83,53.871 ; pad.@47.83,53.871 48.393,53.747 ; pad.@47.83,53.871 48.045,53.657 ; pad.@47.838,53.948 48.44,53.948 ; pad.@47.838,53.948 48.039,54.149 ; 48.039,54.149 47.434,54.149 47.295,54.01 47.295,53.833 47.459,53.669 47.471,53.657 48.045,53.657 ; 48.039,54.149 48.239,54.149 48.44,53.948 ; 48.045,53.657 48.145,53.657 48.235,53.747 48.393,53.747 ; 48.393,53.747 48.641,53.747 ; 48.44,53.948 48.641,53.747 ; 74.805,54.4 74.805,54.199 74.809,54.125 ; 74.805,54.4 74.805,54.601 75.199,54.995 ; 74.805,54.4 75.376,54.971 75.513,54.971 75.592,55.05 75.817,55.05 75.982,55.215 75.982,55.464 75.898,55.548 75.898,55.614 75.815,55.698 75.408,55.698 75.199,55.489 75.199,54.995 ; 74.809,54.125 cw(c62.421,53.577) 74.809,54.103 ; 74.809,54.125 74.809,54.103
